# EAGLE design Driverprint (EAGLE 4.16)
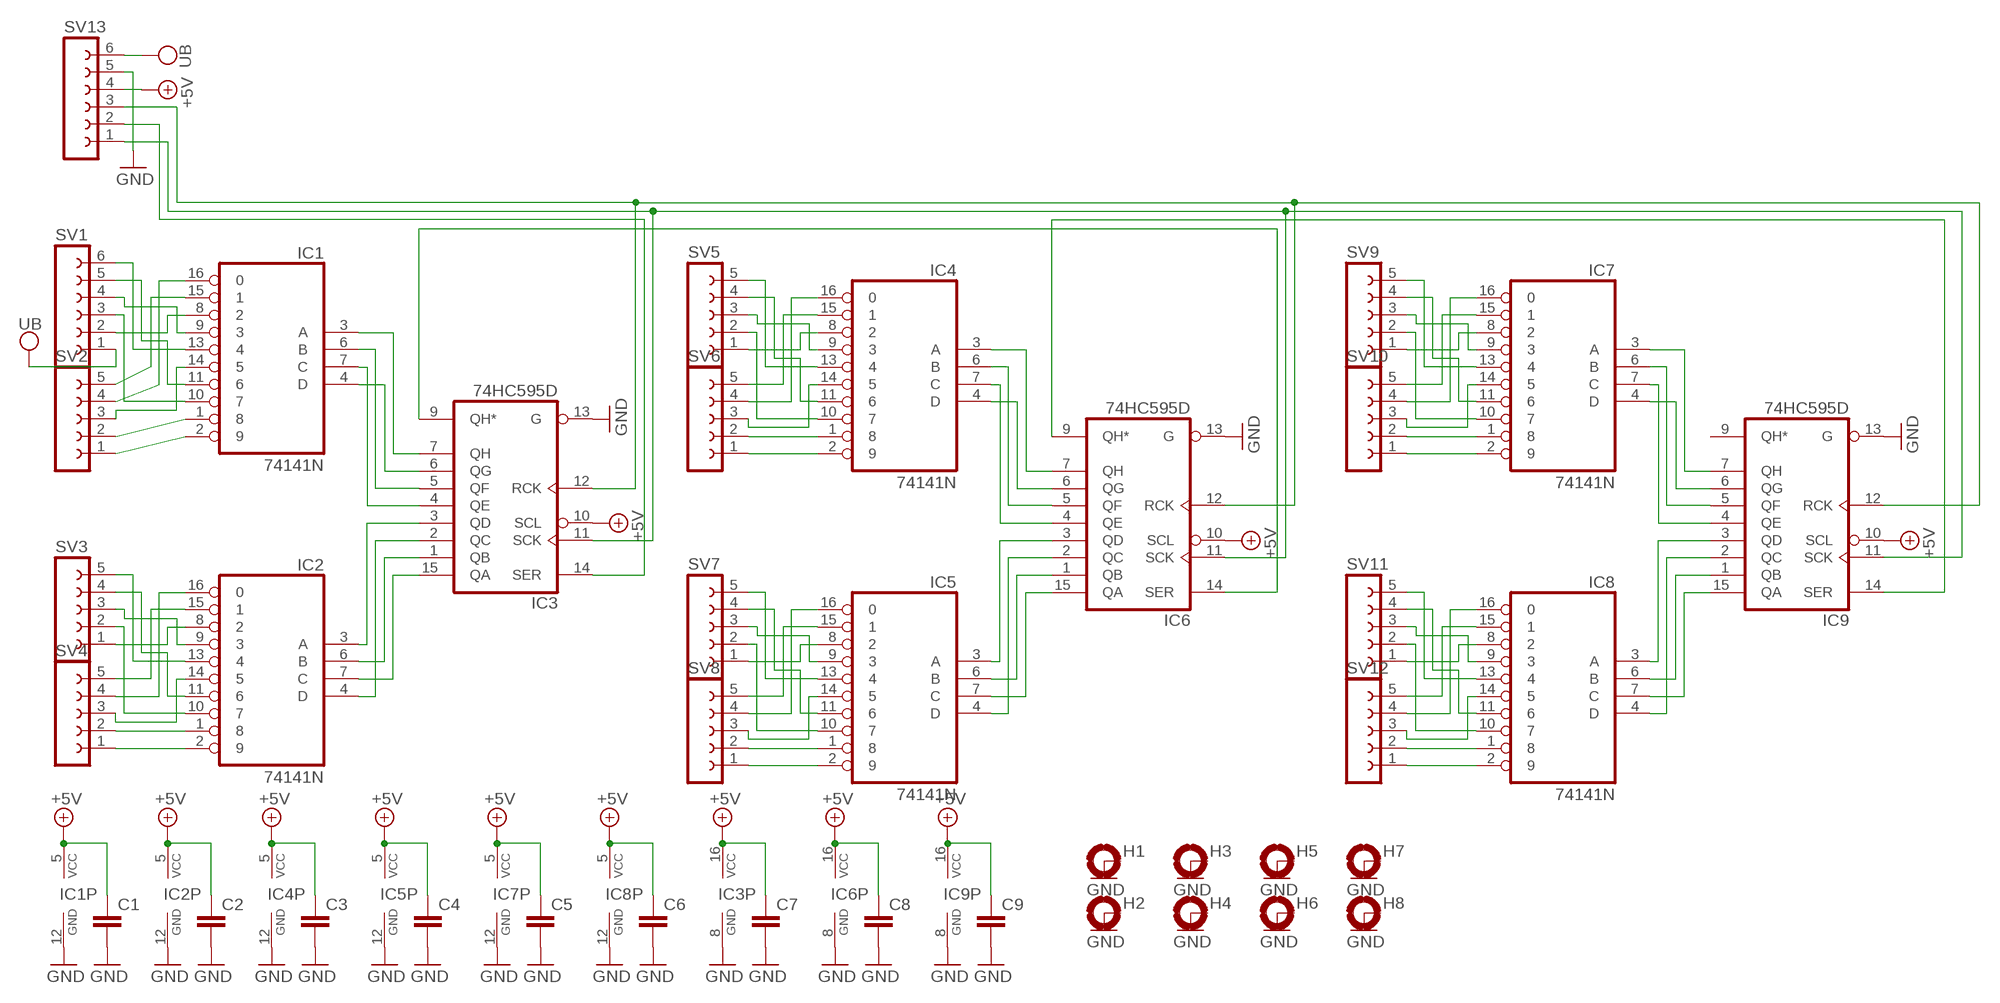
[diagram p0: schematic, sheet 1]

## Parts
C1  C-EUC0805  [C0805]
C2  C-EUC0805  [C0805]
C3  C-EUC0805  [C0805]
C4  C-EUC0805  [C0805]
C5  C-EUC0805  [C0805]
C6  C-EUC0805  [C0805]
C7  C-EUC0805  [C0805]
C8  C-EUC0805  [C0805]
C9  C-EUC0805  [C0805]
H1  MOUNT-PAD-ROUND3.0  [3,0-PAD]
H2  MOUNT-PAD-ROUND3.0  [3,0-PAD]
H3  MOUNT-PAD-ROUND3.0  [3,0-PAD]
H4  MOUNT-PAD-ROUND3.0  [3,0-PAD]
H5  MOUNT-PAD-ROUND3.0  [3,0-PAD]
H6  MOUNT-PAD-ROUND3.0  [3,0-PAD]
H7  MOUNT-PAD-ROUND3.0  [3,0-PAD]
H8  MOUNT-PAD-ROUND3.0  [3,0-PAD]
IC1  74141N  [DIL16]
IC2  74141N  [DIL16]
IC3  74HC595D  [SO16]
IC4  74141N  [DIL16]
IC5  74141N  [DIL16]
IC6  74HC595D  [SO16]
IC7  74141N  [DIL16]
IC8  74141N  [DIL16]
IC9  74HC595D  [SO16]
SV1  FE06-1  [FE06]
SV2  FE05-1  [FE05-1]
SV3  FE05-1  [FE05-1]
SV4  FE05-1  [FE05-1]
SV5  FE05-1  [FE05-1]
SV6  FE05-1  [FE05-1]
SV7  FE05-1  [FE05-1]
SV8  FE05-1  [FE05-1]
SV9  FE05-1  [FE05-1]
SV10  FE05-1  [FE05-1]
SV11  FE05-1  [FE05-1]
SV12  FE05-1  [FE05-1]
SV13  FE06-1  [FE06]

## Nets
+5V: C1.1 C2.1 C3.1 C4.1 C5.1 C6.1 C7.1 C8.1 C9.1 IC1.5(VCC) IC2.5(VCC) IC3.10(SCL) IC3.16(VCC) IC4.5(VCC) IC5.5(VCC) IC6.10(SCL) IC6.16(VCC) IC7.5(VCC) IC8.5(VCC) IC9.10(SCL) IC9.16(VCC) SV13.4
GND: C1.2 C2.2 C3.2 C4.2 C5.2 C6.2 C7.2 C8.2 C9.2 H1.B3,0(MOUNT) H2.B3,0(MOUNT) H3.B3,0(MOUNT) H4.B3,0(MOUNT) H5.B3,0(MOUNT) H6.B3,0(MOUNT) H7.B3,0(MOUNT) H8.B3,0(MOUNT) IC1.12(GND) IC2.12(GND) IC3.8(GND) IC3.13(G) IC4.12(GND) IC5.12(GND) IC6.8(GND) IC6.13(G) IC7.12(GND) IC8.12(GND) IC9.8(GND) IC9.13(G) SV13.5
N$1: IC1.2 SV2.1
N$2: IC1.1 SV2.2
N$3: IC1.13 SV1.6
N$4: IC1.16 SV2.4
N$5: IC1.15 SV2.5
N$6: IC1.11 SV1.5
N$7: IC1.9 SV1.4
N$8: IC1.8 SV1.2
N$9: IC1.14 SV2.3
N$10: IC2.2 SV4.1
N$11: IC1.10 SV1.3
N$12: IC2.1 SV4.2
N$13: IC2.16 SV4.4
N$14: IC2.15 SV4.5
N$15: IC2.14 SV4.3
N$16: IC2.10 SV3.2
N$17: IC2.13 SV3.5
N$18: IC2.11 SV3.4
N$19: IC2.9 SV3.3
N$20: IC2.8 SV3.1
N$21: IC1.3(A) IC3.7(QH)
N$22: IC1.4(D) IC3.6(QG)
N$23: IC1.6(B) IC3.5(QF)
N$24: IC1.7(C) IC3.4(QE)
N$25: IC2.3(A) IC3.3(QD)
N$26: IC2.4(D) IC3.2(QC)
N$27: IC2.6(B) IC3.1(QB)
N$28: IC2.7(C) IC3.15(QA)
N$29: IC4.2 SV6.1
N$30: IC4.1 SV6.2
N$31: IC4.16 SV6.4
N$32: IC4.15 SV6.5
N$33: IC4.14 SV6.3
N$34: IC4.10 SV5.2
N$35: IC4.13 SV5.5
N$36: IC4.11 SV5.4
N$37: IC4.9 SV5.3
N$38: IC4.8 SV5.1
N$39: IC5.2 SV8.1
N$40: IC5.1 SV8.2
N$41: IC5.16 SV8.4
N$42: IC5.15 SV8.5
N$43: IC5.14 SV8.3
N$44: IC5.10 SV7.2
N$45: IC5.13 SV7.5
N$46: IC5.11 SV7.4
N$47: IC5.9 SV7.3
N$48: IC5.8 SV7.1
N$49: IC4.3(A) IC6.7(QH)
N$50: IC4.4(D) IC6.6(QG)
N$51: IC4.6(B) IC6.5(QF)
N$52: IC4.7(C) IC6.4(QE)
N$53: IC5.3(A) IC6.3(QD)
N$54: IC5.4(D) IC6.2(QC)
N$55: IC5.6(B) IC6.1(QB)
N$56: IC5.7(C) IC6.15(QA)
N$57: IC7.2 SV10.1
N$58: IC7.1 SV10.2
N$59: IC7.16 SV10.4
N$60: IC7.15 SV10.5
N$61: IC7.14 SV10.3
N$62: IC7.10 SV9.2
N$63: IC7.13 SV9.5
N$64: IC7.11 SV9.4
N$65: IC7.9 SV9.3
N$66: IC7.8 SV9.1
N$67: IC8.2 SV12.1
N$68: IC8.1 SV12.2
N$69: IC8.16 SV12.4
N$70: IC8.15 SV12.5
N$71: IC8.14 SV12.3
N$72: IC8.10 SV11.2
N$73: IC8.13 SV11.5
N$74: IC8.11 SV11.4
N$75: IC8.9 SV11.3
N$76: IC8.8 SV11.1
N$77: IC7.3(A) IC9.7(QH)
N$78: IC7.4(D) IC9.6(QG)
N$79: IC7.6(B) IC9.5(QF)
N$80: IC7.7(C) IC9.4(QE)
N$81: IC8.3(A) IC9.3(QD)
N$82: IC8.4(D) IC9.2(QC)
N$83: IC8.6(B) IC9.1(QB)
N$84: IC8.7(C) IC9.15(QA)
N$85: IC3.9(QH*) IC6.14(SER)
N$86: IC6.9(QH*) IC9.14(SER)
N$87: IC3.11(SCK) IC6.11(SCK) IC9.11(SCK) SV13.1
N$88: IC3.14(SER) SV13.2
N$89: IC3.12(RCK) IC6.12(RCK) IC9.12(RCK) SV13.3
VSS: SV1.1 SV13.6 ; supply symbol labelled UB
Unconnected: IC9.9(QH*)

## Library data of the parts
C1-C9 = rcl:C-EU: CAPACITOR, European symbol
H1-H8 = holes:MOUNT-PAD-ROUND: MOUNTING PAD, round
IC1 IC2 IC4 IC5 IC7 IC8 = 74xx-eu:74*141: BCD to decimal DECODER/DRIVER
IC3 IC6 IC9 = 74xx-eu:74*595: 8-bit SHIFT REGISTER, output latch
SV1 SV13 = con-lsta:FE06-1: FEMALE HEADER
SV2-SV12 = con-lsta:FE05-1: FEMALE HEADER

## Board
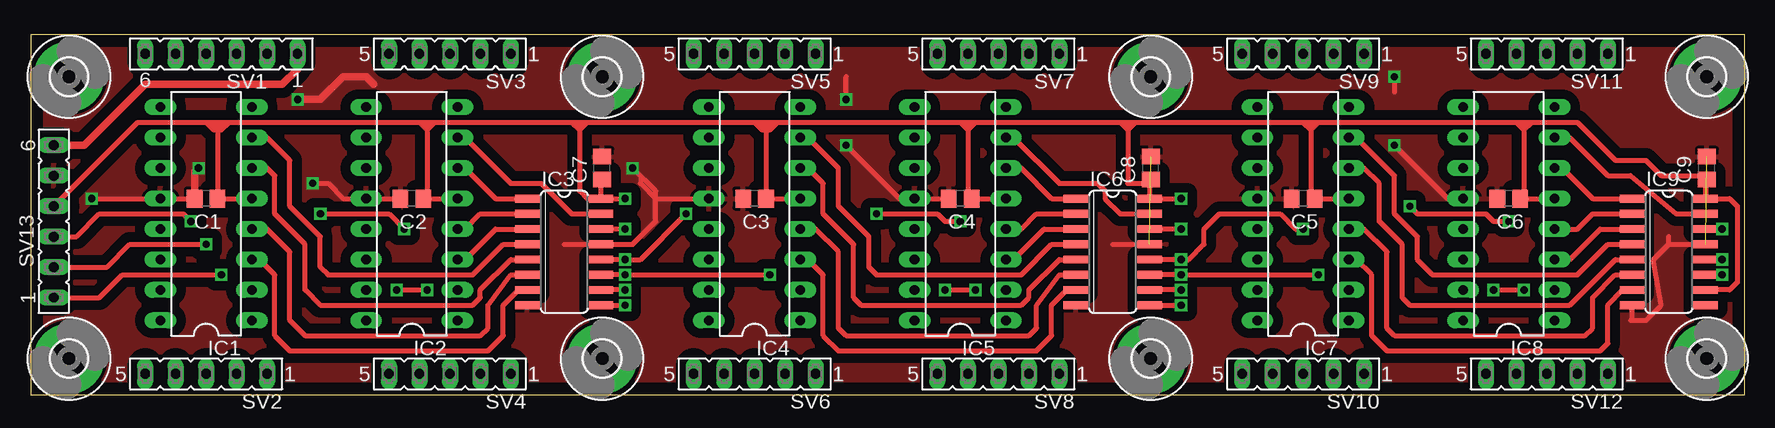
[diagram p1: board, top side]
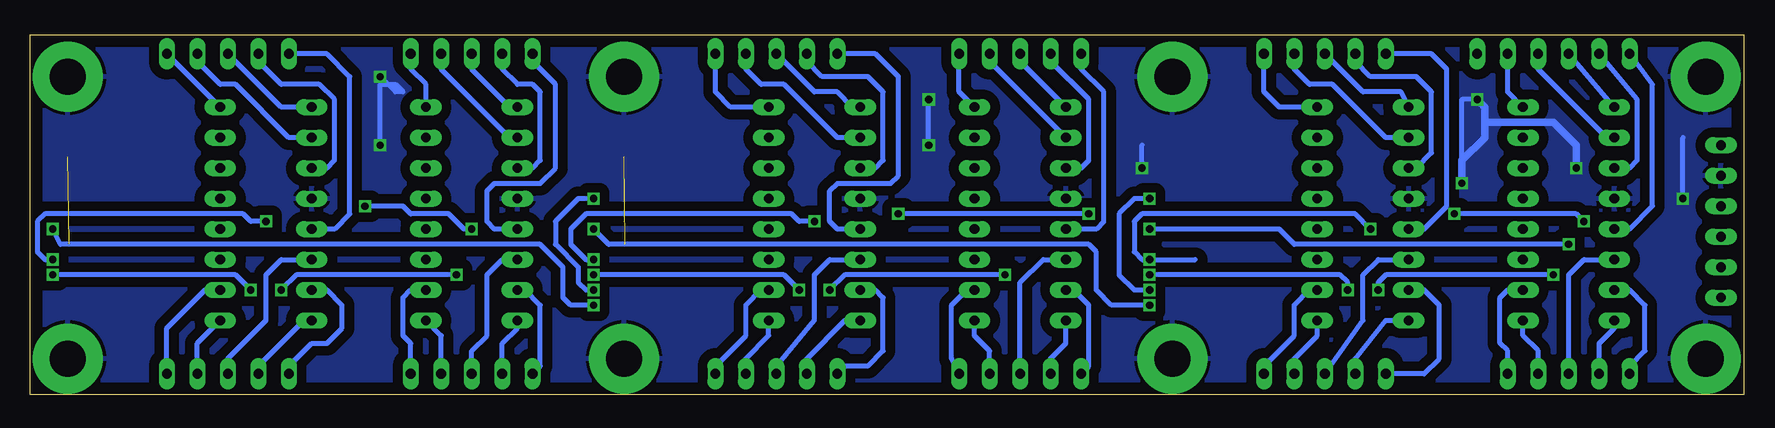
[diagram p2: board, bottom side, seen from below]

Size 142.85 x 30 mm. Coordinates in mm from the lower left corner, seen from the top.
Outline: 0,0 142.85,0 142.85,30 0,30 0,0
Copper layers (1*16): Top 0.035mm / dielectric 1.5mm / Bottom 0.035mm
Design rules "default": minimum track width 10mil, minimum drill 24mil, track to track 8mil, track to pad 8mil, pad to pad 8mil, via to via 8mil, smd to smd 8mil, copper to edge 40mil, drill to drill 8mil, minimum pad ring 10mil, minimum via ring 8mil, stop-mask expansion 4mil, vias tented up to drill 0mil, thermal gap 10mil

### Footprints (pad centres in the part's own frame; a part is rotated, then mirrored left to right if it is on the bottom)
C0805 = smd 1.3 x 1.5: 1 -0.95,0; 2 0.95,0
3,0-PAD = drill 3 pad 5.842 round: B3,0 0,0
DIL16 = drill 0.813 long: 1 -8.89,-3.81; 2 -6.35,-3.81; 3 -3.81,-3.81; 4 -1.27,-3.81; 5 1.27,-3.81; 6 3.81,-3.81; 7 6.35,-3.81; 8 8.89,-3.81; 9 8.89,3.81; 10 6.35,3.81; 11 3.81,3.81; 12 1.27,3.81; 13 -1.27,3.81; 14 -3.81,3.81; 15 -6.35,3.81; 16 -8.89,3.81
SO16 = smd 0.66 x 2.032: 1 -4.445,-3.073; 2 -3.175,-3.073; 3 -1.905,-3.073; 4 -0.635,-3.073; 5 0.635,-3.073; 6 1.905,-3.073; 7 3.175,-3.073; 8 4.445,-3.073; 9 4.445,3.073; 10 3.175,3.073; 11 1.905,3.073; 12 0.635,3.073; 13 -0.635,3.073; 14 -1.905,3.073; 15 -3.175,3.073; 16 -4.445,3.073
FE06 = drill 0.813 long: 1 -6.35,0; 2 -3.81,0; 3 -1.27,0; 4 1.27,0; 5 3.81,0; 6 6.35,0
FE05-1 = drill 0.813 long: 1 -5.08,0; 2 -2.54,0; 3 0,0; 4 2.54,0; 5 5.08,0

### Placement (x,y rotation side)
C1  14.6,16.34 180 top
C2  31.74,16.34 180 top
C3  60.32,16.34 180 top
C4  77.46,16.34 180 top
C5  106.04,16.34 180 top
C6  123.19,16.34 180 top
C7  47.62,18.88 90 top
C8  93.34,18.88 90 top
C9  139.69,18.88 90 top
H1  3.17,26.5 0 top
H2  3.17,3.01 0 top
H3  47.62,26.5 0 top
H4  47.62,3.01 0 top
H5  93.34,26.5 0 top
H6  93.34,3.01 0 top
H7  139.69,26.5 0 top
H8  139.69,3.01 0 top
IC1  14.6,15.08 90 top
IC2  31.74,15.08 90 top
IC3  44.45,11.9 270 top
IC4  60.32,15.08 90 top
IC5  77.46,15.08 90 top
IC6  90.16,11.9 270 top
IC7  106.04,15.08 90 top
IC8  123.19,15.08 90 top
IC9  136.52,11.9 270 top
SV1  15.87,28.41 180 top
SV2  14.6,1.74 180 top
SV3  34.92,28.41 180 top
SV4  34.92,1.74 180 top
SV5  60.32,28.41 180 top
SV6  60.32,1.74 180 top
SV7  80.64,28.41 180 top
SV8  80.64,1.74 180 top
SV9  106.04,28.41 180 top
SV10  106.04,1.74 180 top
SV11  126.36,28.41 180 top
SV12  126.36,1.74 180 top
SV13  1.9,14.44 90 top

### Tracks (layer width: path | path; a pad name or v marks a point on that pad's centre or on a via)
+5V  (via drill 0.6)
  Top 0.406: IC1.5 C1.1 15.55,22.38 15.24,22.7 | 33.02,16.34 C2.1 | IC4.5 C3.1 61.27,22.38 60.96,22.7 | 78.73,16.34 C4.1 | IC7.5 C5.1 106.67,16.34 106.67,22.06 | 124.45,16.34 C6.1 | C9.1 139.69,17.61 139.59,17.51 IC9.16 | IC9.16 139.59,18.15 139.69,18.25 135.88,18.25 134.62,19.52 132.07,19.52 128.9,22.7 125.09,22.7 | 14.6,22.7 8.89,22.7 SV13.4 | 15.87,22.7 16.5,22.7 | 16.5,22.7 32.38,22.7 | 32.38,22.7 33.02,22.7 | 33.02,22.7 33.65,22.7 | 33.65,22.7 44.45,22.7 | 44.45,22.7 45.72,22.7 | 45.72,22.7 46.35,22.7 | 46.35,22.7 60.32,22.7 | 60.32,22.7 60.96,22.7 | 62.23,22.7 77.46,22.7 | 77.46,22.7 78.1,22.7 | 78.1,22.7 78.73,22.7 | 78.73,22.7 90.8,22.7 | 90.8,22.7 91.44,22.7 | 91.44,22.7 92.07,22.7 | 92.07,22.7 106.04,22.7 | 106.04,22.7 106.67,22.7 | 106.67,22.7 107.31,22.7 | 107.31,22.7 123.82,22.7 | 123.82,22.7 124.45,22.7 | 124.45,22.7 125.09,22.7 | 15.87,22.06 16.5,22.7 | 14.6,22.7 15.24,22.06 | 14.6,22.7 15.24,22.7 | 15.24,22.7 15.87,22.06 | 15.24,22.06 15.24,22.7 | 15.24,22.7 15.87,22.7 | 15.87,22.06 15.87,22.7 | 15.24,22.06 15.87,22.06 | 33.02,16.34 IC2.5 | 33.02,22.7 33.02,22.06 | 33.02,22.06 33.02,16.34 | C7.1 47.62,17.61 47.52,17.51 IC3.16 46.98,16.34 | 46.98,16.34 46.35,16.34 45.72,16.98 45.72,22.06 | 45.72,22.7 45.72,22.06 | 78.73,16.34 IC5.5 | 78.73,16.34 78.1,16.34 78.1,22.06 | 78.1,22.7 78.1,22.06 | 93.34,17.61 C8.1 | 93.34,17.61 93.24,17.51 IC6.16 v95.88,16.34 | 93.34,17.61 91.44,17.61 91.44,22.06 | 91.44,22.7 91.44,22.06 | 124.45,16.34 IC8.5 | 124.45,22.7 124.45,22.06 | 124.45,22.06 124.45,16.34 | 124.45,22.06 125.09,22.7 | 123.82,22.7 124.45,22.06 | 91.44,22.06 92.07,22.7 | 90.8,22.7 91.44,22.06 | 106.67,22.7 106.67,22.06 | 106.04,22.7 106.67,22.06 | 106.67,22.06 107.31,22.7
  Top 0.406: 78.1,22.06 78.73,22.7 | 77.46,22.7 78.1,22.06 | 61.59,22.7 62.23,22.7 | 61.59,22.06 62.23,22.7 | 60.96,22.06 61.59,22.06 | 60.32,22.7 60.96,22.06 | 60.96,22.7 60.96,22.06 | 60.96,22.7 61.59,22.7 | 61.59,22.06 61.59,22.7 | 44.45,22.7 45.08,22.7 45.72,22.06 | 45.72,22.06 46.35,22.7 | 32.38,22.7 33.02,22.06 | 33.02,22.06 33.65,22.7 | IC9.10 141.6,8.73 142.23,9.36 142.23,15.71 141.6,16.34 IC9.16 | v49.53,8.73 IC3.10 | 46.98,16.34 v49.53,16.34 | v95.88,8.73 IC6.10
  Bottom 0.406: v49.53,16.34 50.8,16.34 52.07,15.08 52.07,10 50.8,8.73 v49.53,8.73 | v95.88,8.73 96.52,8.73 97.15,9.36 97.15,10.63 99.05,12.54 99.05,14.44 97.15,16.34 v95.88,16.34
GND  (via drill 0.6)  (2 unrouted)
  Top 0.406: IC9.8 133.45,6.29 133.34,6.18 134.62,6.18 135.88,7.46 135.25,11.27 136.52,12.54 | 139.69,12.54 IC9.13 136.52,12.54 | IC8.12 118.1,16.34 v113.66,20.79 | v113.66,26.5 113.66,25.23 | C4.2 72.38,16.34 v67.94,20.79 | v67.94,24.6 67.94,26.5 | IC4.12 52.07,16.34 50.8,17.61 50.8,18.25 v50.16,18.88 52.07,16.98 52.07,14.44 50.16,12.54 IC3.13 44.45,12.54 | 90.16,12.54 IC6.13 | 136.52,12.54 136.52,13.17 | C2.2 26.03,16.34 24.76,17.61 v23.49,17.61 | v5.08,16.34 C1.2
  Top 0.61: v22.22,24.6 24.12,24.6 26.03,26.5 27.93,26.5 28.57,25.87 | C1.2 13.65,18.57 v13.97,18.88
  Bottom 0.406: v113.66,20.79 113.66,25.87 112.39,25.87 111.75,25.23 112.39,25.23 v113.66,26.5 | v67.94,20.79 v67.94,24.6 | v50.16,18.88 50.16,20.79 | v23.49,17.61 23.49,24.6 v22.22,24.6 | v5.08,16.34 5.08,21.42
  Bottom 0.61: v23.49,17.61 23.49,19.52 21.58,21.42 21.58,22.7 | 21.58,22.7 21.58,23.96 v22.22,24.6 | v13.97,18.88 13.97,20.79 15.87,22.7 21.58,22.7
  pour Bottom (isolate 0.813): -0.01,30.31 142.87,30.95 142.87,0.47 -0.01,-0.17
  pour Top (isolate 0.813): -0.01,30.31 142.87,30.31 142.87,-0.17 -0.01,-0.17
N$1
  Bottom 0.406: IC1.2 19.68,8.73 20.31,8.09 20.31,4.28 19.68,3.64 SV2.1
N$2
  Bottom 0.406: IC1.1 18.41,4.92 17.14,3.64 SV2.2
N$3
  Bottom 0.406: SV1.6 7.62,25.87 7.62,15.71 9.52,13.81 IC1.13
N$4
  Bottom 0.406: SV2.4 12.06,4.28 10.79,5.55 IC1.16
N$5
  Bottom 0.406: IC1.15 9.52,8.73 8.25,7.46 8.25,3.64 9.52,2.38 SV2.5
N$6
  Bottom 0.406: SV1.5 8.89,24.6 8.89,19.52 9.52,18.88 IC1.11
N$7
  Bottom 0.406: IC1.9 SV1.4
N$8
  Bottom 0.406: IC1.8 19.68,25.23 SV1.2
N$9
  Bottom 0.406: IC1.14 13.33,11.27 14.6,10 SV2.3
N$10
  Bottom 0.406: IC2.2 36.19,8.73 37.46,7.46 37.46,4.92 40,2.38 SV4.1
N$11
  Bottom 0.406: IC1.10 11.43,21.42 17.14,27.14 SV1.3
N$12
  Bottom 0.406: IC2.1 35.55,4.92 37.46,3.01 SV4.2
N$13
  Bottom 0.406: IC2.16 29.84,6.18 32.38,3.01 SV4.4
N$14
  Bottom 0.406: IC2.15 26.66,8.73 25.39,7.46 25.39,3.01 26.66,1.74 SV4.5
N$15
  Bottom 0.406: SV4.3 31.74,6.18 31.74,10 30.47,11.27 IC2.14
N$16
  Bottom 0.406: SV3.2 37.46,27.14 36.19,25.87 34.29,25.87 29.84,21.42 IC2.10
N$17
  Bottom 0.406: SV3.5 26.03,28.41 24.76,27.14 24.76,15.71 26.66,13.81 IC2.13
N$18
  Bottom 0.406: SV3.4 32.38,27.77 31.11,26.5 27.3,26.5 26.03,25.23 26.03,20.15 27.3,18.88 IC2.11
N$19
  Bottom 0.406: IC2.9 28.57,25.23 31.74,25.23 SV3.3
N$20
  Bottom 0.406: SV3.1 40,25.23 38.73,23.96 IC2.8
N$21
  Top 0.406: IC3.7 40.64,8.73 39.37,7.46 39.37,4.92 38.1,3.64 21.58,3.64 20.31,4.92 20.31,10 19.04,11.27 IC1.3
N$22
  Top 0.406: IC3.6 40,10 38.1,7.46 38.1,5.55 37.46,4.92 22.86,4.92 21.58,6.18 21.58,11.9 19.68,13.81 IC1.4
N$23
  Top 0.406: IC3.5 40,11.27 37.46,8.73 37.46,8.09 36.83,7.46 24.12,7.46 22.86,8.73 22.86,12.54 20.31,15.08 20.31,18.25 19.68,18.88 IC1.6
N$24
  Top 0.406: IC1.7 19.68,21.42 21.58,19.52 21.58,15.71 24.12,13.17 24.12,10.63 24.76,10 36.83,10 39.37,12.54 IC3.4
N$25
  Top 0.406: IC2.3 36.19,11.27 38.73,13.81 IC3.3
N$26
  Top 0.406: IC3.2 37.46,15.08 36.19,13.81 IC2.4
N$27
  Top 0.406: IC3.1 38.73,16.34 36.19,18.88 IC2.6
N$28
  Top 0.406: IC2.7 36.19,21.42 40,17.61 42.54,17.61 45.08,15.08 IC3.15 47.62,15.08
N$29
  Bottom 0.406: SV6.1 66.03,3.01 66.03,7.46 64.77,8.73 IC4.2
N$30
  Bottom 0.406: IC4.1 64.13,4.92 62.86,3.64 SV6.2
N$31
  Bottom 0.406: IC4.16 56.51,4.28 57.78,3.01 SV6.4
N$32
  Bottom 0.406: IC4.15 55.88,8.73 54.61,7.46 54.61,2.38 SV6.5
N$33
  Bottom 0.406: IC4.14 58.41,11.27 60.32,9.36 SV6.3
N$34
  Bottom 0.406: IC4.10 62.86,27.77 SV5.2
N$35
  Bottom 0.406: SV5.5 55.24,27.14 53.34,25.23 53.34,14.44 53.97,13.81 IC4.13
N$36
  Bottom 0.406: SV5.4 57.78,27.77 54.61,24.6 54.61,19.52 55.24,18.88 IC4.11
N$37
  Bottom 0.406: IC4.9 60.32,27.77 SV5.3
N$38
  Bottom 0.406: SV5.1 65.4,25.23 IC4.8
N$39
  Bottom 0.406: IC5.2 81.91,8.73 83.18,7.46 83.18,4.92 85.72,2.38 SV8.1
N$40
  Bottom 0.406: IC5.1 81.27,4.92 83.18,3.01 SV8.2
N$41
  Bottom 0.406: IC5.16 74.92,6.18 78.1,3.01 SV8.4
N$42
  Bottom 0.406: IC5.15 72.38,8.73 71.75,8.09 71.75,3.64 73.02,2.38 74.92,2.38 SV8.5
N$43
  Bottom 0.406: IC5.14 76.19,11.27 77.46,10 77.46,6.18 80.64,2.38 SV8.3
N$44
  Bottom 0.406: SV7.2 83.18,27.14 81.91,25.87 80,25.87 75.56,21.42 IC5.10
N$45
  Bottom 0.406: SV7.5 72.38,28.41 70.48,26.5 70.48,18.25 71.11,17.61 75.56,17.61 76.19,16.98 76.19,14.44 75.56,13.81 IC5.13
N$46
  Bottom 0.406: SV7.4 78.1,27.77 76.83,26.5 73.02,26.5 71.75,25.23 71.75,19.52 72.38,18.88 IC5.11
N$47
  Bottom 0.406: IC5.9 74.29,23.96 75.56,25.23 77.46,25.23 SV7.3
N$48
  Bottom 0.406: SV7.1 85.72,25.23 84.45,23.96 IC5.8
N$49
  Top 0.406: IC6.7 86.35,8.73 85.08,7.46 85.08,4.92 83.81,3.64 67.3,3.64 66.03,4.92 66.03,10 64.77,11.27 IC4.3
N$50
  Top 0.406: IC6.6 85.72,10 83.81,7.46 83.81,5.55 83.18,4.92 67.94,4.92 67.3,5.55 67.3,11.9 65.4,13.81 IC4.4
N$51
  Top 0.406: IC6.5 85.72,11.27 83.18,8.73 83.18,8.09 82.55,7.46 69.21,7.46 68.57,8.09 68.57,12.54 66.03,15.08 66.03,17.61 64.77,18.88 IC4.6
N$52
  Top 0.406: IC4.7 64.77,21.42 67.3,18.88 67.3,15.71 69.84,13.17 69.84,10.63 70.48,10 82.55,10 85.08,12.54 IC6.4
N$53
  Top 0.406: IC6.3 84.45,13.81 81.91,11.27 IC5.3
N$54
  Top 0.406: IC5.4 82.55,13.81 83.81,15.08 IC6.2
N$55
  Top 0.406: IC5.6 82.55,18.88 85.08,16.34 IC6.1
N$56
  Top 0.406: IC6.15 90.8,15.08 89.53,16.34 89.53,16.98 88.89,17.61 85.72,17.61 81.91,21.42 IC5.7
N$57
  Bottom 0.406: IC7.2 111.12,8.73 111.75,8.09 111.75,4.92 111.12,4.28 SV10.1
N$58
  Bottom 0.406: IC7.1 108.58,4.92 SV10.2
N$59
  Bottom 0.406: IC7.16 102.23,5.55 103.5,4.28 SV10.4
N$60
  Bottom 0.406: IC7.15 101.59,8.73 100.32,7.46 100.32,2.38 SV10.5
N$61
  Bottom 0.406: IC7.14 103.5,11.27 104.77,10 104.77,4.92 106.04,3.64 SV10.3
N$62
  Bottom 0.406: SV9.2 108.58,27.14 102.86,21.42 IC7.10
N$63
  Bottom 0.406: SV9.5 100.96,27.77 99.05,25.87 99.05,18.88 100.32,17.61 104.13,17.61 104.77,16.98 104.77,14.44 104.13,13.81 IC7.13
N$64
  Bottom 0.406: SV9.4 103.5,27.14 102.23,25.87 100.96,25.87 100.32,25.23 100.32,19.52 100.96,18.88 IC7.11
N$65
  Bottom 0.406: SV9.3 106.04,27.14 102.86,23.96 IC7.9
N$66
  Bottom 0.406: SV9.1 111.12,27.14 109.85,25.87 IC7.8
N$67
  Bottom 0.406: IC8.2 128.27,8.73 131.44,5.55 SV12.1
N$68
  Bottom 0.406: SV12.2 128.9,4.28 IC8.1
N$69
  Bottom 0.406: IC8.16 120.01,6.18 123.82,2.38 SV12.4
N$70
  Bottom 0.406: IC8.15 118.1,8.73 116.83,7.46 116.83,5.55 118.1,4.28 119.38,4.28 121.28,2.38 SV12.5
N$71
  Bottom 0.406: SV12.3 126.36,3.01 123.19,6.18 123.19,10 121.91,11.27 IC8.14
N$72
  Bottom 0.406: SV11.2 128.9,27.77 126.99,25.87 125.72,25.87 121.28,21.42 IC8.10
N$73
  Bottom 0.406: SV11.5 118.1,28.41 116.2,26.5 116.2,15.08 117.47,13.81 IC8.13
N$74
  Bottom 0.406: SV11.4 123.82,27.77 121.91,25.87 118.74,25.87 117.47,24.6 117.47,19.52 118.1,18.88 IC8.11
N$75
  Bottom 0.406: SV11.3 121.91,23.96 IC8.9
N$76
  Bottom 0.406: IC8.8 SV11.1
N$77
  Top 0.406: IC9.7 132.71,8.73 131.44,7.46 131.44,4.28 130.81,3.64 113.02,3.64 111.75,4.92 111.75,10 110.48,11.27 IC7.3
N$78
  Top 0.406: IC7.4 111.12,13.81 113.02,11.9 113.02,5.55 113.66,4.92 129.53,4.92 130.17,5.55 130.17,8.09 132.07,10 IC9.6
N$79
  Top 0.406: IC9.5 132.07,11.27 128.27,7.46 114.93,7.46 114.3,8.09 114.3,12.54 112.39,14.44 112.39,17.61 111.12,18.88 IC7.6
N$80
  Top 0.406: IC9.4 131.44,12.54 128.9,10 116.83,10 115.56,11.27 115.56,13.17 113.66,15.08 113.66,18.25 110.48,21.42 IC7.7
N$81
  Top 0.406: IC9.3 130.81,13.81 128.27,11.27 IC8.3
N$82
  Top 0.406: IC9.2 130.17,15.08 128.9,13.81 IC8.4
N$83
  Top 0.406: IC9.1 130.17,16.34 127.63,18.88 IC8.6
N$84
  Top 0.406: IC8.7 128.27,21.42 131.44,18.25 133.34,18.25 137.16,15.08 IC9.15 139.69,15.08
N$85  (via drill 0.6)
  Top 0.406: IC3.9 v49.53,7.46 | v95.88,13.81 IC6.14
  Bottom 0.406: v49.53,7.46 52.7,7.46 53.97,8.73 53.97,11.9 54.61,12.54 94.61,12.54 v95.88,13.81
N$86  (via drill 0.6)
  Top 0.406: IC6.9 v95.88,7.46 | v140.97,13.81 IC9.14
  Bottom 0.406: v95.88,7.46 97.78,7.46 98.42,8.09 98.42,10.63 100.32,12.54 140.33,12.54 v140.97,13.81
N$87  (via drill 0.6)
  Top 0.406: v61.59,10 v49.53,10 IC3.11 | v76.19,8.73 v78.73,8.73 | IC6.11 v95.88,10 v107.31,10 | v121.91,8.73 v124.45,8.73 | v140.97,10 IC9.11 | SV13.1 5.71,8.09 7.62,10 v15.87,10 | v30.47,8.73 v33.02,8.73
  Bottom 0.406: v61.59,10 74.92,10 v76.19,8.73 | v78.73,8.73 80,10 v95.88,10 | v107.31,10 120.64,10 v121.91,8.73 | v124.45,8.73 125.72,10 v140.97,10 | v49.53,10 33.65,10 33.02,9.36 v33.02,8.73 | v30.47,8.73 30.47,9.36 29.84,10 v15.87,10
N$88  (via drill 0.6)
  Top 0.406: v14.6,12.54 8.25,12.54 6.34,10.63 SV13.2 | v49.53,13.81 IC3.14
  Bottom 0.406: v14.6,12.54 37.46,12.54 38.73,13.81 v49.53,13.81
N$89  (via drill 0.6)
  Top 0.406: v54.61,15.08 50.8,11.27 v49.53,11.27 IC3.12 | v70.48,15.08 75.56,15.08 76.19,14.44 v77.46,14.44 | IC6.12 v95.88,11.27 96.52,11.27 97.78,12.54 97.78,13.81 99.05,15.08 104.13,15.08 105.41,13.81 v106.04,13.81 | v140.97,11.27 IC9.12 | v123.19,14.44 121.91,14.44 121.28,15.08 115.56,15.08 v114.93,15.71 | v31.11,13.81 29.84,15.08 v24.12,15.08 | v13.33,14.44 12.7,15.08 5.71,15.08 3.8,13.17 SV13.3
  Bottom 0.406: v54.61,15.08 v70.48,15.08 | v77.46,14.44 78.73,14.44 79.37,15.08 96.52,15.08 97.78,13.81 97.78,12.54 96.52,11.27 v95.88,11.27 | v140.97,11.27 141.6,11.27 142.23,11.9 142.23,14.44 141.6,15.08 125.09,15.08 124.45,14.44 v123.19,14.44 | v114.93,15.71 111.75,15.71 111.12,15.08 107.94,15.08 106.67,13.81 v106.04,13.81 | 45.72,11.27 v49.53,11.27 50.16,11.27 50.8,11.9 50.8,14.44 50.16,15.08 32.38,15.08 v31.11,13.81 | v24.12,15.08 13.97,15.08 v13.33,14.44
VSS
  Top 0.61: SV1.1 22.22,27.14 20.95,25.87 9.52,25.87 4.44,20.79 SV13.6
